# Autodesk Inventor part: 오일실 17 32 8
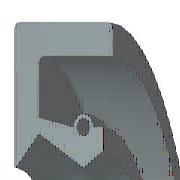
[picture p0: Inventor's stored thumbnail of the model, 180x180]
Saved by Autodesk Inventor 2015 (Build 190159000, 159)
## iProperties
IsCustomPart: 1
Created: 2012-02
Part Number: 오일실 17 32 8
Material: 고무
Description: 오일-실
Document SubType Name: Modeling
Standard: KS B 2804
Designer: mduedu
Standards Organization: KS
Language: ko-KR
Size Designation: D - 17 32 8
Categories: <MemberInstance><Categories><Category DisplayName="샤프트 부품" InternalName="7f7aeb1f-a693-4053-b835-cee3144e0d98" Mnemonic="SHFT"><Category DisplayName="실링" Intern
Density: 0.93 g/cm^3
Appearance: 고무 - 검은색 - 버전 1.1
Author: mduedu
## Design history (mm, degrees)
revolve "본체" stored, may be unused: angle "d17" = 90 deg
revolve "스프링1" stored, may be unused: angle "d18" = 90 deg
body "Solid1"
sketch "스케치1"
  geometry: L1 (0, 16)-(8, 16); L2 (8, 14.25)-(1.75, 14.25); L3 (1.75, 10.25)-(4.9, 8.5); L4 (4.9, 8.5)-(0, 8.5); L5 (0, 0)-(9.586, 0) reference; L6 (4.9, 8.5)-(6.3, 9.375); L7 (0, 18)-(0, -3) reference; L8 (-1.941, 0)-(11.507, 0) reference; L9 (4.2, 10.6)-(1.75, 11.21); L10 (1.75, 11.21)-(1.75, 14.25); L11 (0, 16)-(0, 8.588); L12 (4.9, 8.5)-(0, 8.5); L13 (1.75, 10.25)-(0.152, 8.528); L14 (8, 16)-(8, 14.25); L15 (5.6, 10.6)-(6.3, 10.6); L16 (6.3, 10.6)-(6.3, 9.375); C1 r 0.455 at (4.9, 10.6); A1 r 0.7 centre (4.9, 10.6) between (5.6, 10.6) and (4.2, 10.6); A2 r 0.088 centre (0.088, 8.588) between (0, 8.588) and (0.152, 8.528); 1 further point
  constraints: 28 end point, 5 horizontal alignment, 5 point on line, 4 point on circle, 4 vertical alignment, 3 centre point, 3 tangent, 2 collinear, 2 horizontal, 2 perpendicular, 1 coincident, 1 parallel
  dimensions: "d0" = 32 diameter of L1 L5 (= SD2); "d1" = 1.75 distance of L1.end L2.start (= SD); "d2" = 0.91 diameter of C1 (= SPDI); "d3" = 1.4 diameter of A1 (= SPDA); "d4" = 17 diameter of L3.end L5 (= NND); "d5" = 20.5 diameter of L3.start L5 (= TKDM); "d7" = 22.42 diameter of L9.end L5 (= TKDM + 0.24 x SWDT); "d8" = 1.75 distance between parallel lines of L11 L10 (= SD); "d9" = 4.9 distance from line of L11 C1.centre (= SPDST); "d10" = 21.2 diameter of C1.centre L5 (= HLDM); "d11" = 0.0875 radius of A2 (= 0.25 x LAB); "d12" = 6.3 distance between parallel lines of L11 L16 (= SDI); "d13" = 18.75 diameter of L6.end L5 (= ABDM); "d14" = 8 distance from line of L11 L1.end (= SWDT)
fillet "모깎기1" dims "d6" = 0.3 (= RR)
other parameters: "SD2" = 32 [user parameter; used in 1 equation term], "SWDT" = 8 [user parameter; used in 2 equation terms], "RR" = 0.3 [user parameter; used in 1 equation term], "SD" = 1.75 [user parameter; used in 2 equation terms], "NND" = 17 [user parameter; used in 1 equation term], "SPDA" = 1.4 [user parameter; used in 1 equation term], "SPDI" = 0.91 [user parameter; used in 1 equation term], "TKDM" = 20.5 [user parameter; used in 2 equation terms], "HLDM" = 21.2 [user parameter; used in 1 equation term], "ABDM" = 18.75 [user parameter; used in 1 equation term], "SDI" = 6.3 [user parameter; used in 1 equation term], "SPDST" = 4.9 [user parameter; used in 1 equation term], "LAB" = 0.35 [user parameter; used in 1 equation term], "d15" = 0, "d16" = 0, "d19" = 0
